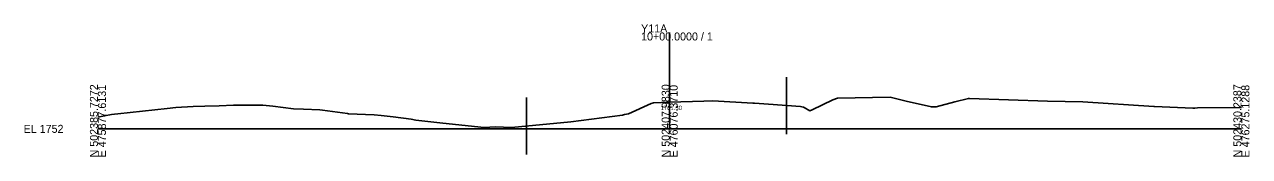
# Model space of a CAD drawing. Extents: x -26 to 403, y -10 to 5098.
# Drawn here: x -25.7 to 402.8, y -9.7 to 36.6 of the extents above; entities that cross this region are included whole.
import ezdxf

# ---------------------------------------------------------------- set-up
doc = ezdxf.new("R2010")
doc.units = 0
for name, color, linetype in [('Exist Cross Section Cell', 7, 'Continuous'), ('Exist XS Center Line Elevation Label', 7, 'Continuous'), ('Exist XS Ground Line', 7, 'Continuous'), ('Scratch_Level_5', 7, 'Continuous')]:
    doc.layers.add(name, color=color, linetype=linetype)

msp = doc.modelspace()

# ---------------------------------------------------------------- linework, layer by layer
at = {"layer": 'Exist Cross Section Cell'}
for p, q in [((200, 0), (200, 33.75)), ((0, 0), (200, 0)), ((200, 0), (400, 0))]:
    msp.add_line(p, q, dxfattribs=at)
at = {"layer": 'Exist XS Ground Line'}
msp.add_lwpolyline([(0, 4.1), (2.34, 4.52), (4.74, 5.01), (5.75, 5.14), (6.9, 5.3), (15.57, 6.24), (24.27, 7.08), (27.28, 7.52), (33.32, 7.84), (37.35, 7.95), (42.39, 8.03), (47.41, 8.3), (51.43, 8.35), (57.69, 8.32), (61.15, 7.96), (68.46, 7.04), (71.96, 6.84), (77.61, 6.66), (78.5, 6.52), (87.27, 5.36), (87.67, 5.31), (96.68, 4.89), (99.05, 4.67), (103.23, 4.16), (109.63, 3.35), (111.22, 3.02), (112.23, 2.88), (120.67, 2.03), (135.12, 0.5), (139.05, 0.65), (144.63, 0.52), (165.47, 2.49), (183.47, 4.81), (184.24, 4.97), (185.55, 5.26), (193.48, 8.88), (194.35, 9.1), (200, 9.3), (211.97, 9.73), (215.05, 9.83), (229.05, 9.04), (229.67, 9.01), (234.57, 8.64), (245.79, 7.78), (246.22, 7.7), (246.78, 7.57), (247.11, 7.42), (249.04, 6.35), (249.89, 6.66), (257.05, 10.13), (258.74, 10.75), (277.11, 11.04), (282.69, 9.71), (291.55, 7.7), (293.25, 7.66), (299.76, 9.46), (304.51, 10.67), (304.84, 10.64), (332.17, 9.66), (344.48, 9.47), (369.34, 7.8), (369.66, 7.78), (383.07, 7.28), (383.72, 7.29), (384.67, 7.39), (400, 7.48)], dxfattribs=at)
at = {"layer": 'Scratch_Level_5'}
for p, q in [((240.92, 18.14), (240.92, -1.86)), ((149.96, 11.01), (149.96, -8.99))]:
    msp.add_line(p, q, dxfattribs=at)

# ---------------------------------------------------------------- texts
at = {"layer": 'Exist Cross Section Cell'}
for s, p in [('Y11A', (190, 33.75)), ('10+00.0000 / 1', (190, 30.95)), ('EL 1752', (-26, -1.4))]:
    msp.add_text(s, height=2.8, dxfattribs=at).set_placement(p)
for s, p in [('N 502385.7272', (0, -10)), ('E 475877.6131', (2.8, -10)), ('N 502407.9830', (200, -10)), ('E 476076.3710', (202.8, -10)), ('N 502430.2387', (400, -10)), ('E 476275.1288', (402.8, -10))]:
    msp.add_text(s, height=2.8, rotation=90, dxfattribs=at).set_placement(p)
at = {"layer": 'Exist XS Center Line Elevation Label'}
msp.add_text('1761.30', height=1.5, dxfattribs=at).set_placement((196.82, 6.61))

doc.saveas('drawing.dxf')
